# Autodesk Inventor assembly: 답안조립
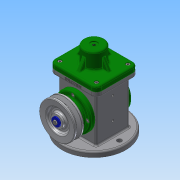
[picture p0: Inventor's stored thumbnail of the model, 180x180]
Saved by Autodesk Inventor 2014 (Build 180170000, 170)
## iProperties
Created: 2018-10
Part Number: 답안조립
Document SubType Name: Assembly
Designer: NET
Author: NET
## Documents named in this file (18)
- C:\Users\NET\Desktop\481007V1023\답안조립.iam
- C:\Users\NET\Desktop\481007V1023\답안본체.ipt
- C:\Users\NET\Desktop\481007V1023\편심축.ipt
- C:\Users\NET\Desktop\481007V1023\베어링 17 x 40 x 12.ipt
- C:\Users\NET\Desktop\481007V1023\뒤커버.ipt
- C:\Users\NET\Desktop\481007V1023\볼트 M4 x 8.ipt
- C:\Users\NET\Desktop\481007V1023\앞커버.ipt
- C:\Users\NET\Desktop\481007V1023\V-벨트풀리.ipt
- C:\Users\NET\Desktop\481007V1023\키 4 x 4 x 12.ipt
- C:\Users\NET\Desktop\481007V1023\볼트 M4 x 10.ipt
- C:\Users\NET\Desktop\481007V1023\와셔 4x16.ipt
- C:\Users\NET\Desktop\481007V1023\오일 실 17 30 8.ipt
- C:\Users\NET\Desktop\481007V1023\링크.ipt
- C:\Users\NET\Desktop\481007V1023\클레비스 핀 6 x 22.ipt
- 클레비스 핀 6 x 22.ipt
- C:\Users\NET\Desktop\481007V1023\슬라이더.ipt
- C:\Users\NET\Desktop\481007V1023\E-링.ipt
- C:\Users\NET\Desktop\481007V1023\덮개.ipt
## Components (2 placed, 2 different names)
1. V-벨트풀리:1
2. E-링:1
